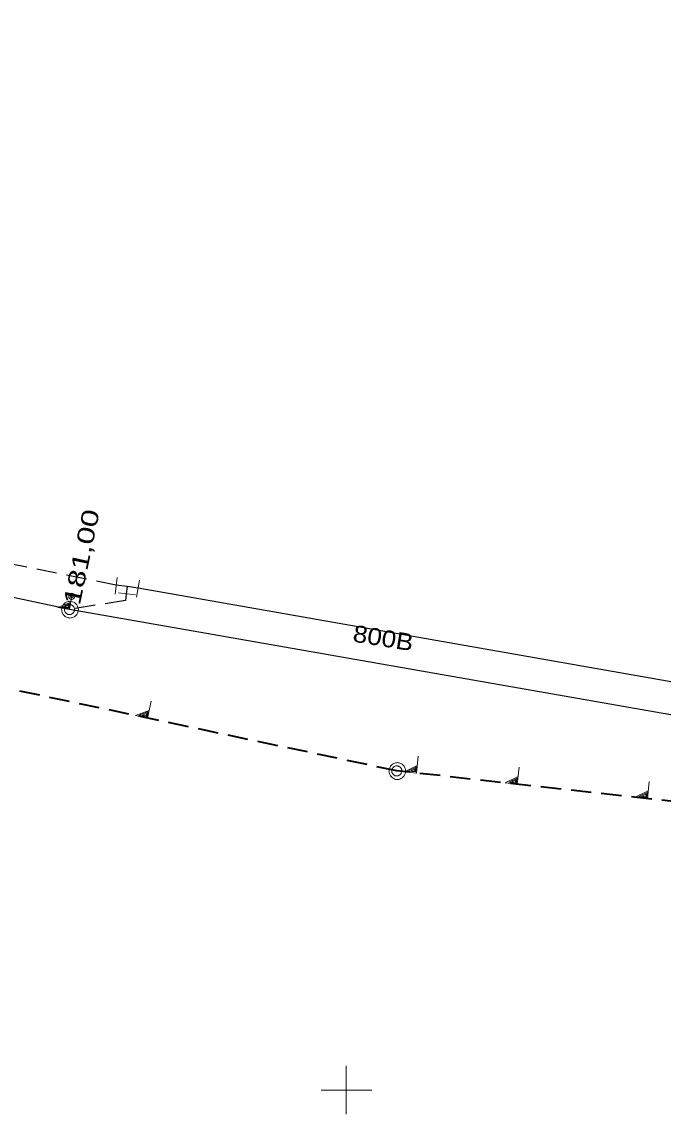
# Model space of a CAD drawing. Extents: x -740851 to -738888, y -1041382 to -1040235.
# Drawn here: x -740219.2 to -740181.2, y -1040451.4 to -1040386.8 of the extents above; entities that cross this region are included whole.
import ezdxf

# ---------------------------------------------------------------- set-up
doc = ezdxf.new("R2010")
doc.units = 0
doc.header["$LTSCALE"] = 0.4
doc.linetypes.add('MEDIUM_DASHED', pattern=[4.5, 3, -1.5])
for name, color, linetype, lineweight in [('1', 7, 'Continuous', 13), ('18', 7, 'Continuous', 13), ('8', 7, 'Continuous', 13)]:
    doc.layers.add(name, color=color, linetype=linetype, lineweight=lineweight)

msp = doc.modelspace()

# ---------------------------------------------------------------- linework, layer by layer
at = {"layer": '1'}
for p, q in [((-740200, -1040448.571), (-740200, -1040451.429)), ((-740201.48, -1040450), (-740198.48, -1040450))]:
    msp.add_line(p, q, dxfattribs=at)
at = {"layer": '18', "lineweight": 25}
for p, q in [((-740216.38, -1040421.57), (-740235.03, -1040417.63)), ((-740175.27, -1040428.77), (-740216.38, -1040421.57))]:
    msp.add_line(p, q, dxfattribs=at)
at = {"layer": '18', "linetype": 'MEDIUM_DASHED', "lineweight": 40}
for p, q in [((-740197.01, -1040431.12), (-740252.95, -1040419.28)), ((-740151.51, -1040436.14), (-740197.01, -1040431.12))]:
    msp.add_line(p, q, dxfattribs=at)
at = {"layer": '18'}
for points in [[(-740216.21, -1040420.613), (-740216.377, -1040421.568), (-740217.059, -1040421.449), (-740216.302, -1040421.137)], [(-740216.369, -1040421.224), (-740216.417, -1040421.502), (-740216.853, -1040421.426), (-740216.364, -1040421.225)], [(-740216.436, -1040421.316), (-740216.461, -1040421.455), (-740216.684, -1040421.416), (-740216.432, -1040421.317)], [(-740211.553, -1040426.995), (-740211.764, -1040427.995), (-740212.478, -1040427.844), (-740211.669, -1040427.544)], [(-740211.743, -1040427.633), (-740211.804, -1040427.924), (-740212.26, -1040427.827), (-740211.738, -1040427.634)], [(-740211.817, -1040427.727), (-740211.848, -1040427.872), (-740212.082, -1040427.823), (-740211.813, -1040427.728)], [(-740195.739, -1040430.246), (-740195.849, -1040431.246), (-740196.563, -1040431.167), (-740195.799, -1040430.795)], [(-740195.863, -1040430.889), (-740195.895, -1040431.18), (-740196.351, -1040431.13), (-740195.858, -1040430.89)], [(-740195.927, -1040430.988), (-740195.943, -1040431.134), (-740196.177, -1040431.108), (-740195.922, -1040430.989)], [(-740189.775, -1040430.904), (-740189.885, -1040431.904), (-740190.599, -1040431.825), (-740189.836, -1040431.453)], [(-740189.899, -1040431.547), (-740189.931, -1040431.838), (-740190.387, -1040431.788), (-740189.894, -1040431.548)], [(-740189.963, -1040431.646), (-740189.979, -1040431.792), (-740190.213, -1040431.766), (-740189.958, -1040431.647)], [(-740182.072, -1040431.754), (-740182.182, -1040432.754), (-740182.896, -1040432.675), (-740182.132, -1040432.302)], [(-740182.196, -1040432.397), (-740182.228, -1040432.688), (-740182.684, -1040432.638), (-740182.191, -1040432.397)], [(-740182.26, -1040432.496), (-740182.276, -1040432.642), (-740182.51, -1040432.616), (-740182.255, -1040432.497)]]:
    msp.add_lwpolyline(points, dxfattribs=at)
for points in [[(-740215.85, -1040421.58), (-740215.86, -1040421.53), (-740215.86, -1040421.48), (-740215.88, -1040421.43), (-740215.9, -1040421.38), (-740215.92, -1040421.33), (-740215.95, -1040421.29), (-740215.98, -1040421.25), (-740216.02, -1040421.21), (-740216.06, -1040421.18), (-740216.1, -1040421.15), (-740216.15, -1040421.13), (-740216.2, -1040421.11), (-740216.25, -1040421.09), (-740216.3, -1040421.09), (-740216.35, -1040421.08), (-740216.4, -1040421.09), (-740216.45, -1040421.09), (-740216.5, -1040421.11), (-740216.55, -1040421.13), (-740216.6, -1040421.15), (-740216.64, -1040421.18), (-740216.68, -1040421.21), (-740216.72, -1040421.25), (-740216.75, -1040421.29), (-740216.78, -1040421.33), (-740216.8, -1040421.38), (-740216.82, -1040421.43), (-740216.84, -1040421.48), (-740216.84, -1040421.53), (-740216.85, -1040421.58), (-740216.84, -1040421.63), (-740216.84, -1040421.68), (-740216.82, -1040421.73), (-740216.8, -1040421.78), (-740216.78, -1040421.83), (-740216.75, -1040421.87), (-740216.72, -1040421.91), (-740216.68, -1040421.95), (-740216.64, -1040421.98), (-740216.6, -1040422.01), (-740216.55, -1040422.03), (-740216.5, -1040422.05), (-740216.45, -1040422.07), (-740216.4, -1040422.07), (-740216.35, -1040422.08), (-740216.3, -1040422.07), (-740216.25, -1040422.07), (-740216.2, -1040422.05), (-740216.15, -1040422.03), (-740216.1, -1040422.01), (-740216.06, -1040421.98), (-740216.02, -1040421.95), (-740215.98, -1040421.91), (-740215.95, -1040421.87), (-740215.92, -1040421.83), (-740215.9, -1040421.78), (-740215.88, -1040421.73), (-740215.86, -1040421.68), (-740215.86, -1040421.63)], [(-740216.08, -1040421.57), (-740216.08, -1040421.54), (-740216.086, -1040421.51), (-740216.092, -1040421.48), (-740216.104, -1040421.45), (-740216.122, -1040421.42), (-740216.14, -1040421.396), (-740216.158, -1040421.372), (-740216.182, -1040421.348), (-740216.206, -1040421.33), (-740216.23, -1040421.312), (-740216.26, -1040421.294), (-740216.29, -1040421.282), (-740216.32, -1040421.276), (-740216.35, -1040421.27), (-740216.38, -1040421.27), (-740216.41, -1040421.27), (-740216.44, -1040421.276), (-740216.47, -1040421.282), (-740216.5, -1040421.294), (-740216.53, -1040421.312), (-740216.554, -1040421.33), (-740216.578, -1040421.348), (-740216.602, -1040421.372), (-740216.62, -1040421.396), (-740216.638, -1040421.42), (-740216.656, -1040421.45), (-740216.668, -1040421.48), (-740216.674, -1040421.51), (-740216.68, -1040421.54), (-740216.68, -1040421.57), (-740216.68, -1040421.6), (-740216.674, -1040421.63), (-740216.668, -1040421.66), (-740216.656, -1040421.69), (-740216.638, -1040421.72), (-740216.62, -1040421.744), (-740216.602, -1040421.768), (-740216.578, -1040421.792), (-740216.554, -1040421.81), (-740216.53, -1040421.828), (-740216.5, -1040421.846), (-740216.47, -1040421.858), (-740216.44, -1040421.864), (-740216.41, -1040421.87), (-740216.38, -1040421.87), (-740216.35, -1040421.87), (-740216.32, -1040421.864), (-740216.29, -1040421.858), (-740216.26, -1040421.846), (-740216.23, -1040421.828), (-740216.206, -1040421.81), (-740216.182, -1040421.792), (-740216.158, -1040421.768), (-740216.14, -1040421.744), (-740216.122, -1040421.72), (-740216.104, -1040421.69), (-740216.092, -1040421.66), (-740216.086, -1040421.63), (-740216.08, -1040421.6)], [(-740196.48, -1040431.13), (-740196.49, -1040431.08), (-740196.49, -1040431.03), (-740196.51, -1040430.98), (-740196.53, -1040430.93), (-740196.55, -1040430.88), (-740196.58, -1040430.84), (-740196.61, -1040430.8), (-740196.65, -1040430.76), (-740196.69, -1040430.73), (-740196.73, -1040430.7), (-740196.78, -1040430.68), (-740196.83, -1040430.66), (-740196.88, -1040430.64), (-740196.93, -1040430.64), (-740196.98, -1040430.63), (-740197.03, -1040430.64), (-740197.08, -1040430.64), (-740197.13, -1040430.66), (-740197.18, -1040430.68), (-740197.23, -1040430.7), (-740197.27, -1040430.73), (-740197.31, -1040430.76), (-740197.35, -1040430.8), (-740197.38, -1040430.84), (-740197.41, -1040430.88), (-740197.43, -1040430.93), (-740197.45, -1040430.98), (-740197.47, -1040431.03), (-740197.47, -1040431.08), (-740197.48, -1040431.13), (-740197.47, -1040431.18), (-740197.47, -1040431.23), (-740197.45, -1040431.28), (-740197.43, -1040431.33), (-740197.41, -1040431.38), (-740197.38, -1040431.42), (-740197.35, -1040431.46), (-740197.31, -1040431.5), (-740197.27, -1040431.53), (-740197.23, -1040431.56), (-740197.18, -1040431.58), (-740197.13, -1040431.6), (-740197.08, -1040431.62), (-740197.03, -1040431.62), (-740196.98, -1040431.63), (-740196.93, -1040431.62), (-740196.88, -1040431.62), (-740196.83, -1040431.6), (-740196.78, -1040431.58), (-740196.73, -1040431.56), (-740196.69, -1040431.53), (-740196.65, -1040431.5), (-740196.61, -1040431.46), (-740196.58, -1040431.42), (-740196.55, -1040431.38), (-740196.53, -1040431.33), (-740196.51, -1040431.28), (-740196.49, -1040431.23), (-740196.49, -1040431.18)], [(-740196.71, -1040431.12), (-740196.71, -1040431.09), (-740196.716, -1040431.06), (-740196.722, -1040431.03), (-740196.734, -1040431), (-740196.752, -1040430.97), (-740196.77, -1040430.946), (-740196.788, -1040430.922), (-740196.812, -1040430.898), (-740196.836, -1040430.88), (-740196.86, -1040430.862), (-740196.89, -1040430.844), (-740196.92, -1040430.832), (-740196.95, -1040430.826), (-740196.98, -1040430.82), (-740197.01, -1040430.82), (-740197.04, -1040430.82), (-740197.07, -1040430.826), (-740197.1, -1040430.832), (-740197.13, -1040430.844), (-740197.16, -1040430.862), (-740197.184, -1040430.88), (-740197.208, -1040430.898), (-740197.232, -1040430.922), (-740197.25, -1040430.946), (-740197.268, -1040430.97), (-740197.286, -1040431), (-740197.298, -1040431.03), (-740197.304, -1040431.06), (-740197.31, -1040431.09), (-740197.31, -1040431.12), (-740197.31, -1040431.15), (-740197.304, -1040431.18), (-740197.298, -1040431.21), (-740197.286, -1040431.24), (-740197.268, -1040431.27), (-740197.25, -1040431.294), (-740197.232, -1040431.318), (-740197.208, -1040431.342), (-740197.184, -1040431.36), (-740197.16, -1040431.378), (-740197.13, -1040431.396), (-740197.1, -1040431.408), (-740197.07, -1040431.414), (-740197.04, -1040431.42), (-740197.01, -1040431.42), (-740196.98, -1040431.42), (-740196.95, -1040431.414), (-740196.92, -1040431.408), (-740196.89, -1040431.396), (-740196.86, -1040431.378), (-740196.836, -1040431.36), (-740196.812, -1040431.342), (-740196.788, -1040431.318), (-740196.77, -1040431.294), (-740196.752, -1040431.27), (-740196.734, -1040431.24), (-740196.722, -1040431.21), (-740196.716, -1040431.18), (-740196.71, -1040431.15)]]:
    msp.add_lwpolyline(points, close=True, dxfattribs=at)
for centre, radius in [((-740216.242, -1040420.789), 0.183), ((-740216.242, -1040420.787), 0.0902)]:
    msp.add_circle(centre, radius, dxfattribs=at)
at = {"layer": '8'}
for p, q in [((-740213.68, -1040420.67), (-740213.55, -1040419.67)), ((-740212.405, -1040420.84), (-740212.229, -1040419.84)), ((-740212.48, -1040420.711), (-740213.48, -1040420.58))]:
    msp.add_line(p, q, dxfattribs=at)
at = {"layer": '8', "lineweight": 25}
msp.add_line((-740212.964, -1040420.214), (-740213.02, -1040420.64), dxfattribs=at)
at = {"layer": '8', "linetype": 'MEDIUM_DASHED', "lineweight": 25}
for points in [[(-740213.61, -1040420.13), (-740245.88, -1040413.69), (-740267.67, -1040408.79), (-740291.79, -1040403.21), (-740294.311, -1040395.753), (-740297.337, -1040386.803)], [(-740213.02, -1040420.64), (-740213.072, -1040421.036), (-740216.38, -1040421.57)]]:
    msp.add_lwpolyline(points, dxfattribs=at)
at = {"layer": '8', "lineweight": 25}
for points in [[(-740212.31, -1040420.3), (-740212.964, -1040420.214), (-740213.61, -1040420.13)], [(-740166.074, -1040428.12), (-740167.273, -1040427.971), (-740178.09, -1040426.33), (-740212.31, -1040420.3)]]:
    msp.add_lwpolyline(points, dxfattribs=at)

# ---------------------------------------------------------------- texts
at = {"layer": '18'}
for s, rotation, width, p in [('181,00', 78.012, 1.4, (-740215.773, -1040421.368)), ('800B', 350.75, 1.15, (-740199.663, -1040423.461))]:
    msp.add_text(s, height=1, rotation=rotation, dxfattribs=dict(at, width=width)).set_placement(p)

doc.saveas('drawing.dxf')
